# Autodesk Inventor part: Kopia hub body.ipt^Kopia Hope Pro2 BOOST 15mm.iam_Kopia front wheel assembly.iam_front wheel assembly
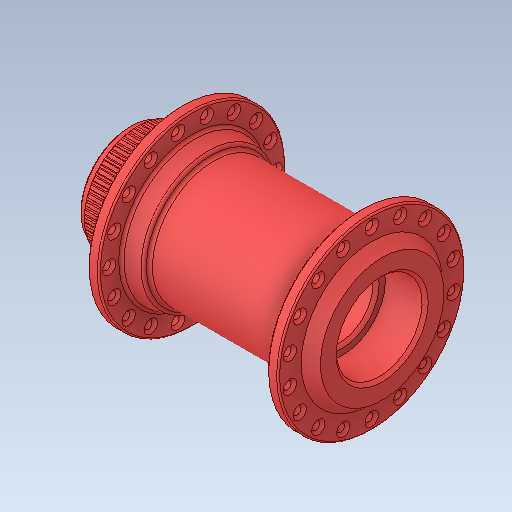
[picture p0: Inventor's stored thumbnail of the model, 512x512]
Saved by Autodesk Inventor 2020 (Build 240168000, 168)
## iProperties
Created: 2017-09
Part Number: Kopia hub body.ipt^Kopia Hope Pro2 BOOST 15mm.iam_Kopia front wheel assembly.iam_front wheel assembly
Material: Ogólny
Document SubType Name: Modeling
Designer: Tomasz
Density: 1 g/cm^3
Appearance: Domyślna
Sending System: SolidWorks 2017
Last Author: Tomasz
Last Saved: 2017-09-11
Author: Tomasz
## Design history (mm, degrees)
feature "hub body.ipt"
node "Bryła1"
